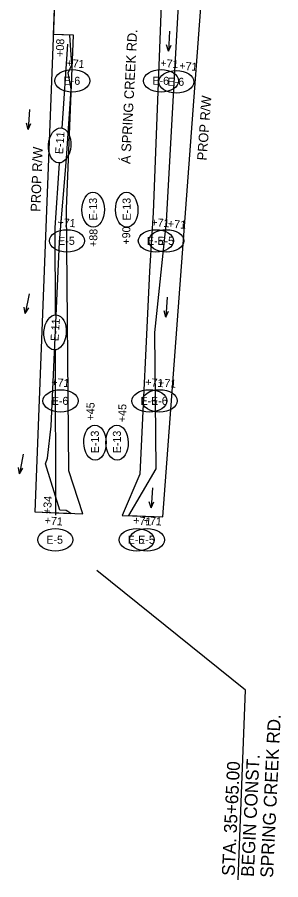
# Model space of a CAD drawing. Extents: x 670673 to 672613, y 705754 to 707185.
# Drawn here: x 671654 to 671819, y 705754 to 706293 of the extents above; entities that cross this region are included whole.
import ezdxf

# ---------------------------------------------------------------- set-up
doc = ezdxf.new("R2010")
doc.units = 0
for name, color, linetype in [('R_Draft', 7, 'Continuous'), ('R_Erosion Clearing Right', 7, 'Continuous'), ('R_Erosion Stage 2', 7, 'Continuous'), ('R_Flow Arrows Clear and Grub', 7, 'Continuous'), ('R_No Plot', 7, 'Continuous'), ('R_Proposed Sidewalk', 7, 'Continuous')]:
    doc.layers.add(name, color=color, linetype=linetype)

# ---------------------------------------------------------------- blocks, each defined once
blk = doc.blocks.new('FLOW ARROW')
at = {"layer": 'R_Proposed Sidewalk'}
for p, q in [((-1.78, 0.09), (10.79, 0.09)), ((10.79, 0.09), (6.94, 1.49)), ((10.79, 0.09), (6.94, -1.31))]:
    blk.add_line(p, q, dxfattribs=at)

msp = doc.modelspace()

# ---------------------------------------------------------------- linework, layer by layer
at = {"layer": 'R_Draft'}
msp.add_line((671796.62, 705872.44), (671703.72, 705947.27), dxfattribs=at)
msp.add_lwpolyline([(671792.04, 705753.98), (671796.62, 705872.44)], dxfattribs=at)
at = {"layer": 'R_Erosion Clearing Right'}
for centre in [(671688.51, 706253.17), (671743.94, 706253.17), (671685.24, 706153.17), (671740.67, 706153.17), (671681.13, 706053.17), (671736.56, 706053.17), (671677.86, 705966.39), (671728.64, 705966.39)]:
    msp.add_ellipse(centre, major_axis=(10.96, 0.01), ratio=0.638788, dxfattribs=at)
at = {"layer": 'R_Erosion Stage 2'}
for points in [[(671685.41, 706276.02), (671681.86, 706223.53)], [(671680.38, 706201.67), (671677.66, 706161.37), (671677.78, 706106.65)], [(671677.83, 706085.46), (671678.08, 705981.79)]]:
    msp.add_lwpolyline(points, dxfattribs=at)
for centre, major_axis in [((671753.41, 706252.56), (10.96, 0.01)), ((671680.62, 706212.83), (0.71, 10.93)), ((671701.52, 706172.63), (-0.12, 10.96)), ((671722.48, 706172.63), (-0.12, 10.96)), ((671747.21, 706153.17), (10.96, 0.01)), ((671677.76, 706096), (0.71, 10.93)), ((671743.09, 706053.17), (10.96, 0.01)), ((671702.64, 706027.15), (-0.12, 10.96)), ((671716.43, 706027.15), (-0.12, 10.96)), ((671735.18, 705966.39), (10.96, 0.01))]:
    msp.add_ellipse(centre, major_axis=major_axis, ratio=0.638788, dxfattribs=at)
at = {"layer": 'R_No Plot'}
for points in [[(671746.65, 706370.95), (671738.9, 706170.96), (671736.59, 706134.14), (671730.58, 706007.46), (671719.66, 705981.68), (671745.05, 705980.7), (671776.29, 706399.8)], [(671758.58, 706371.83), (671747.12, 706165.34), (671739.85, 706095.86), (671740.57, 706010.73), (671723.67, 705981.53), (671745.05, 705980.7), (671776.29, 706399.8)], [(671678.45, 706328.53), (671665.11, 705983.79), (671695.08, 705982.63), (671686.29, 706009.49), (671684.95, 706173.17), (671689.15, 706281.65), (671676.71, 706282.13), (671677.45, 706298.12)], [(671678.45, 706328.53), (671665.11, 705983.79), (671687.68, 705982.92), (671684.56, 705984.65), (671680.72, 705984.86), (671671.76, 706013.9), (671672.99, 706017.37), (671675.3, 706037.42), (671680.5, 706152.63), (671684.9, 706204.58), (671687.85, 706248.08), (671686, 706258.19), (671688.26, 706263.11), (671686.85, 706281.74), (671676.71, 706282.13), (671677.45, 706298.12)]]:
    msp.add_lwpolyline(points, dxfattribs=at)

# ---------------------------------------------------------------- block references
at = {"layer": 'R_Flow Arrows Clear and Grub'}
for p, rotation in [((671749.06, 706282.46), -93.33218862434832), ((671661.51, 706233.52), -93.33218862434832), ((671661.13, 706118.36), -101.054555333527), ((671747.5, 706116.3), -93.33218862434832), ((671657.49, 706018.16), -101.054555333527), ((671738.28, 705997.05), -93.33218862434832)]:
    msp.add_blockref('FLOW ARROW', p, dxfattribs=dict(at, rotation=rotation))

# ---------------------------------------------------------------- texts
at = {"layer": 'R_Draft'}
for s, height, rotation, p in [('Á SPRING CREEK RD.', 6, 87.0336, (671724.71, 706201.11)), ('PROP R/W', 6, 85.7371, (671772.35, 706203.25)), ('PROP R/W', 6, 87.7825, (671668.48, 706171.28)), ('SPRING CREEK RD.', 8, 87.2574, (671813.78, 705755.08)), ('BEGIN CONST.', 8, 87.2574, (671801.8, 705755.66)), ('STA. 35+65.00', 8, 87.2574, (671789.81, 705756.23))]:
    msp.add_text(s, height=height, rotation=rotation, dxfattribs=at).set_placement(p)
at = {"layer": 'R_Erosion Clearing Right'}
for s, rotation, p in [('+71', 355.8145, (671684.64, 706261.92)), ('+71', 355.8145, (671743.29, 706261.92)), ('E-6', 0.0539, (671683.05, 706250.7)), ('E-6', 0.0539, (671738.48, 706250.7)), ('+71', 355.8145, (671679.05, 706162.48)), ('+71', 355.8145, (671737.7, 706162.48)), ('E-5', 0.0539, (671679.65, 706150.7)), ('E-5', 0.0539, (671735.08, 706150.7)), ('+71', 355.8145, (671675.23, 706062.54)), ('+71', 355.8145, (671733.88, 706062.54)), ('E-6', 0.0539, (671675.67, 706050.7)), ('E-6', 0.0539, (671731.1, 706050.7)), ('+71', 355.8145, (671671.1, 705976.1)), ('+71', 355.8145, (671726.37, 705976.1)), ('E-5', 0.0539, (671672.27, 705963.92)), ('E-5', 0.0539, (671723.05, 705963.92))]:
    msp.add_text(s, height=4.999, rotation=rotation, dxfattribs=at).set_placement(p)
at = {"layer": 'R_Erosion Stage 2'}
for s, rotation, p in [('+08', 88.1988, (671683.15, 706268.09)), ('+71', 355.8145, (671755.16, 706260.22)), ('E-6', 0.0539, (671747.95, 706250.09)), ('E-11', 86.2788, (671682.72, 706207.27)), ('E-13', 90.609, (671704.04, 706165.96)), ('E-13', 90.609, (671725.01, 706165.96)), ('+71', 355.8145, (671748, 706161.52)), ('+88', 88.7484, (671703.99, 706149.31)), ('+90', 88.7484, (671724.53, 706150.79)), ('E-5', 0.0539, (671741.62, 706150.7)), ('E-11', 86.2788, (671679.86, 706090.43)), ('+71', 355.8145, (671741.9, 706062.19)), ('+45', 88.7484, (671702.16, 706040.9)), ('+45', 88.7484, (671722.04, 706039.88)), ('E-6', 0.0539, (671737.64, 706050.7)), ('E-13', 90.609, (671705.17, 706020.48)), ('E-13', 90.609, (671718.96, 706020.48)), ('+34', 85.8145, (671675.1, 705982.31)), ('+71', 355.8145, (671732.91, 705976.1)), ('E-5', 0.0539, (671729.59, 705963.92))]:
    msp.add_text(s, height=4.999, rotation=rotation, dxfattribs=at).set_placement(p)

doc.saveas('drawing.dxf')
